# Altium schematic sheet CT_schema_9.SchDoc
size 277 x 170 mm
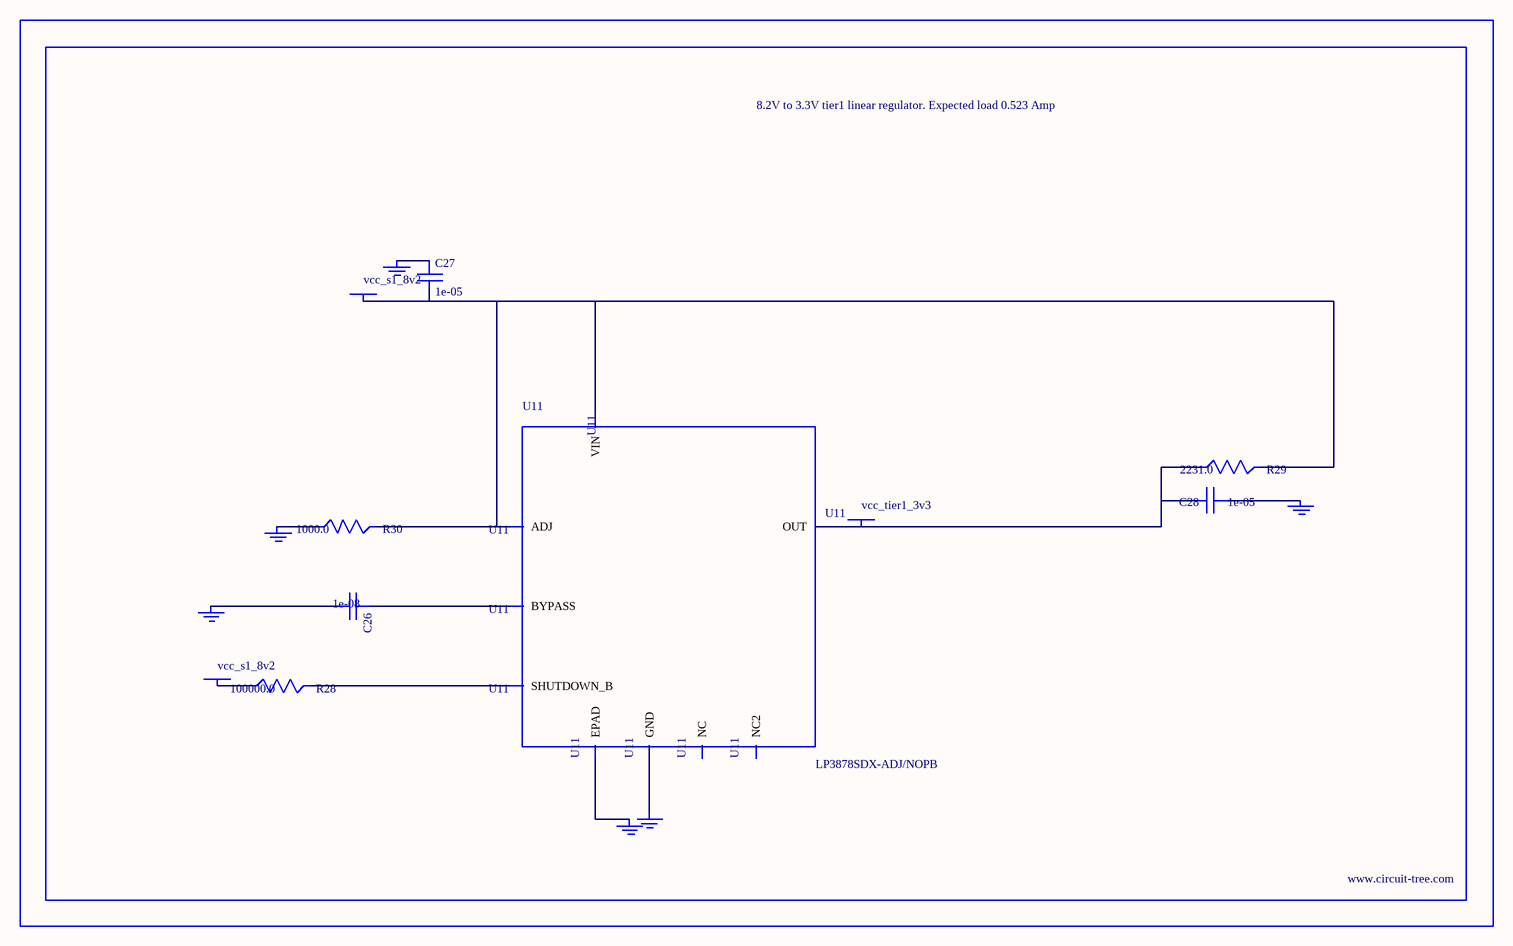
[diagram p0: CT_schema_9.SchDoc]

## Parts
BORDER8  (no value)
C26  1e-08  [C0402]
C27  1e-05  [C1206]
C28  1e-05  [C1210]
GND_INSTANCE_8_0  (no value)
GND_INSTANCE_8_1  (no value)
GND_INSTANCE_8_2  (no value)
GND_INSTANCE_8_3  (no value)
GND_INSTANCE_8_4  (no value)
GND_INSTANCE_8_5  (no value)
POWER_INSTANCE_8_0  vcc_s1_8v2
POWER_INSTANCE_8_1  vcc_s1_8v2
POWER_INSTANCE_8_2  vcc_tier1_3v3
R28  100000.0  [R0603]
R29  2231.0  [R0603]
R30  1000.0  [R0603]
U11  LP3878SDX-ADJ/NOPB  [WSON-8]

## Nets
NetC26_1: C26.1 U11.1(BYPASS)
NetC26_2: C26.2 GND_INSTANCE_8_0.0(GND)
NetC27_1: C27.1 GND_INSTANCE_8_1.0(GND)
NetC27_2: C27.2 POWER_INSTANCE_8_0.0(PWR) R29.2 R30.2 U11.4(VIN) U11.6(ADJ)
NetC28_1: C28.1 GND_INSTANCE_8_2.0(GND)
NetC28_2: C28.2 POWER_INSTANCE_8_2.0(PWR) R29.1 U11.5(OUT)
NetGND_INSTANCE_8_3_0: GND_INSTANCE_8_3.0(GND) R30.1
NetGND_INSTANCE_8_4_0: GND_INSTANCE_8_4.0(GND) U11.PAD(EPAD)
NetGND_INSTANCE_8_5_0: GND_INSTANCE_8_5.0(GND) U11.3(GND)
NetPOWER_INSTANCE_8_1_0: POWER_INSTANCE_8_1.0(PWR) R28.1
NetR28_2: R28.2 U11.8(SHUTDOWN_B)

Not connected (* = marked no-connect by the designer): U11 2(NC) 7(NC2)

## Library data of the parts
BORDER8 = BORDER_PAGE8
C26 = C0402C103K3RAC
C27 = C1206C106K3RACTU
C28 = GRM32DR61E106MA12L
GND_INSTANCE_8_0-GND_INSTANCE_8_5 = GND
POWER_INSTANCE_8_0-POWER_INSTANCE_8_2 = PWR
R28 = RC0603JR-07100KL
R29 = R29
R30 = RC0603JR-071KL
